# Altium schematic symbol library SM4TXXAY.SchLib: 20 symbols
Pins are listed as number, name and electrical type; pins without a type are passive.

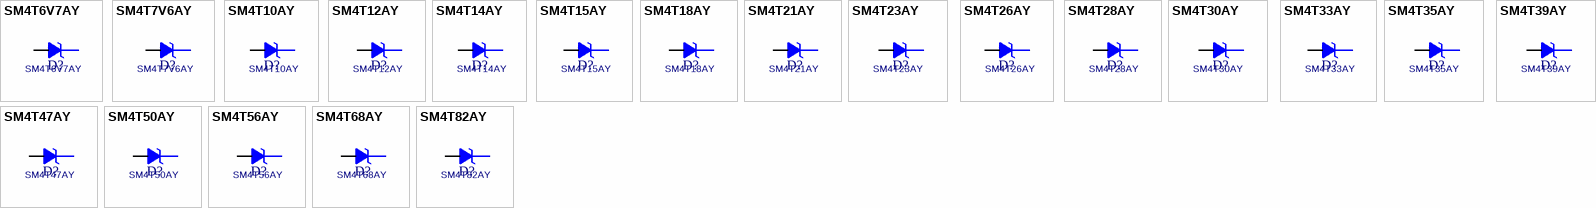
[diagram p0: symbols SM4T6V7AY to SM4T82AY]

## SM4T6V7AY
designator D?
footprint ST_SMA
pins: 1 K, 2 A

## SM4T7V6AY
designator D?
footprint ST_SMA
pins: 1 K, 2 A

## SM4T10AY
designator D?
footprint ST_SMA
pins: 1 K, 2 A

## SM4T12AY
designator D?
footprint ST_SMA
pins: 1 K, 2 A

## SM4T14AY
designator D?
footprint ST_SMA
pins: 1 K, 2 A

## SM4T15AY
designator D?
footprint ST_SMA
pins: 1 K, 2 A

## SM4T18AY
designator D?
footprint ST_SMA
pins: 1 K, 2 A

## SM4T21AY
designator D?
footprint ST_SMA
pins: 1 K, 2 A

## SM4T23AY
designator D?
footprint ST_SMA
pins: 1 K, 2 A

## SM4T26AY
designator D?
footprint ST_SMA
pins: 1 K, 2 A

## SM4T28AY
designator D?
footprint ST_SMA
pins: 1 K, 2 A

## SM4T30AY
designator D?
footprint ST_SMA
pins: 1 K, 2 A

## SM4T33AY
designator D?
footprint ST_SMA
pins: 1 K, 2 A

## SM4T35AY
designator D?
footprint ST_SMA
pins: 1 K, 2 A

## SM4T39AY
designator D?
footprint ST_SMA
pins: 1 K, 2 A

## SM4T47AY
designator D?
footprint ST_SMA
pins: 1 K, 2 A

## SM4T50AY
designator D?
footprint ST_SMA
pins: 1 K, 2 A

## SM4T56AY
designator D?
footprint ST_SMA
pins: 1 K, 2 A

## SM4T68AY
designator D?
footprint ST_SMA
pins: 1 K, 2 A

## SM4T82AY
designator D?
footprint ST_SMA
pins: 1 K, 2 A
